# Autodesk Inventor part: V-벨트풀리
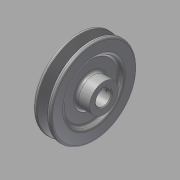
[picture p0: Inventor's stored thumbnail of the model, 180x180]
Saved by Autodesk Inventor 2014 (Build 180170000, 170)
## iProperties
Created: 2015-09
Part Number: V-벨트풀리
Material: 강철, 연강
Document SubType Name: Modeling
Designer: mduedu
Density: 1 g/cm^3
Appearance: 강철
Author: mduedu
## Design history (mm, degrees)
sketch "스케치1"
  geometry: L1 (-10, 0)-(10, 0); L2 (-10, 0)-(-10, 48); L3 (-10, 48)-(-5.976, 48); L4 (-5.976, 48)-(-2.154, 35.5); L5 (-2.154, 35.5)-(2.154, 35.5); L6 (2.154, 35.5)-(5.976, 48); L7 (5.976, 48)-(10, 48); L8 (10, 48)-(10, 0); L9 (0, 0)-(0, 35.5); L10 (-10, 43.5)-(10, 43.5); 3 further points
  constraints: 20 end point, 6 point on line, 3 perpendicular, 2 midpoint, 2 parallel, 2 symmetric about line, 1 coincident, 1 collinear, 1 equal length, 1 horizontal, 1 vertical, 1 vertical alignment
  dimensions: "d0" = 20 distance between parallel lines of L8 L2; "d2" = 96 diameter of L3 L1; "d3" = 87 diameter of L10 L1; "d4" = 4.5 distance between parallel lines of L10 L3 (derived); "d5" = 8 distance between parallel lines of L5 L10; "d6" = 9.2 distance of point (4.6, 43.5) point (-4.6, 43.5); "d7" = 34 deg angle of L6 L4
revolve "회전1" sketch "스케치1" stored, may be unused: angle "d8" = 90 deg
sketch "스케치2"
  geometry: C1 r 16 at (0, 0); 1 further point
  constraints: 1 centre point, 1 coincident
  dimensions: "d9" = 32 diameter of C1
extrude "돌출1" join sketch "스케치2" distance "d10" = 11; taper "d11" = 0 deg
fillet "모깎기1" dims "d12" = 1, "d13" = 0.5, "d14" = 2
sketch "스케치3"
  geometry: C1 r 16 at (0, 0) reference; C2 r 32 at (0, 0); 1 further point
  constraints: 1 centre point, 1 coincident
  dimensions: "d15" = 64 diameter of C2
extrude "돌출2" cut sketch "스케치3" distance "d16" = 4; taper "d17" = 0 deg
fillet "모깎기2" dims "d18" = 3
fillet "모깎기3" dims "d19" = 3
fillet "모깎기4" dims "d20" = 3
sketch "스케치4"
  geometry: C1 r 8.5 at (0, 0); 1 further point
  constraints: 1 centre point, 1 coincident
  dimensions: "d21" = 17 diameter of C1
extrude "돌출3" cut sketch "스케치4" stored distance "d22" = 4; taper "d23" = 0 deg
sketch "스케치5"
  geometry: L1 (-2.5, 8.124)-(2.5, 8.124); L2 (2.5, 8.124)-(2.5, 10.8); L3 (2.5, 10.8)-(-2.5, 10.8); L4 (-2.5, 10.8)-(-2.5, 8.124); A1 r 8.5 centre (0, 0) between (-2.5, 8.124) and (2.5, 8.124) reference; 2 further points
  constraints: 8 end point, 3 point on circle, 2 parallel, 1 horizontal, 1 perpendicular, 1 vertical alignment
  dimensions: "d24" = 5 distance of L2.end L3.end; "d26" = 19.3 distance from line of L3 point (0, -8.5)
extrude "돌출4" cut sketch "스케치5" stored distance "d27" = 4; taper "d28" = 0 deg
chamfer "모따기1" distance "d29" = 1; stored, may be unused: second distance "d30" = 2, angle "d31" = 45 deg
node "작업 평면1"
sketch "스케치6"
  geometry: L1 (-11, 16)-(-11, -16) reference; 2 further points
  constraints: 1 horizontal alignment
  dimensions: "d32" = 5 distance from line of point (-6, 0) L1
hole "구멍1" sketch "스케치6" at (-6, 0) diameter "d33" = 3.242; stored, may be unused: countersink angle "d37" = 90 deg, drill point angle "d39" = 118 deg; dims "d34" = 6, "d35" = 4, "d36" = 2, "d38" = 8
node "솔리드1"
mirror "대칭1"
